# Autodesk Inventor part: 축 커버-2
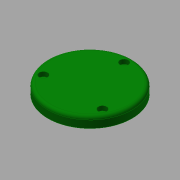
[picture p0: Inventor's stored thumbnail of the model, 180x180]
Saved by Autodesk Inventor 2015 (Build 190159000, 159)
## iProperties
Created: 2015-10
Part Number: 축 커버-2
Document SubType Name: Modeling
Designer: mdu
Density: 1 g/cm^3
Material: 강철, 연강
Appearance: 진녹색
Author: mdu
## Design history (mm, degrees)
sketch "스케치1"
  geometry: C1 r 40 at (0, 0) reference; C2 r 26 at (0, 0) reference; 1 further point
  node "참조1"
  node "참조2"
extrude "돌출1" new body sketch "스케치1" distance "d0" = 10; taper "d1" = 0 deg
extrude "돌출2" join sketch "스케치1" distance "d2" = 3; taper "d3" = 0 deg
sketch "스케치2"
  geometry: C1 r 20 at (0, 0); 1 further point
  constraints: 1 centre point, 1 coincident
  dimensions: "d13" = 40 diameter of C1
extrude "돌출3" cut sketch "스케치2" distance "d14" = 3; taper "d15" = 0 deg
sketch "스케치3"
  geometry: C1 r 1.621 at (0, 32.5) reference; 1 further point
hole "구멍2" sketch "스케치3" at (0, 32.5) diameter "d16" = 4.5; stored, may be unused: countersink angle "d20" = 90 deg, drill point angle "d22" = 118 deg; dims "d17" = 6, "d18" = 8, "d19" = 4.4, "d21" = 8
fillet "모깎기1" dims "d26" = 3, "d27" = 0.3
chamfer "모따기1" distance "d28" = 1; stored, may be unused: second distance "d29" = 2, angle "d30" = 45 deg
node "솔리드1"
pattern_circular "원형 패턴1" dims angle "d24" = 360 deg
node "참조3"
